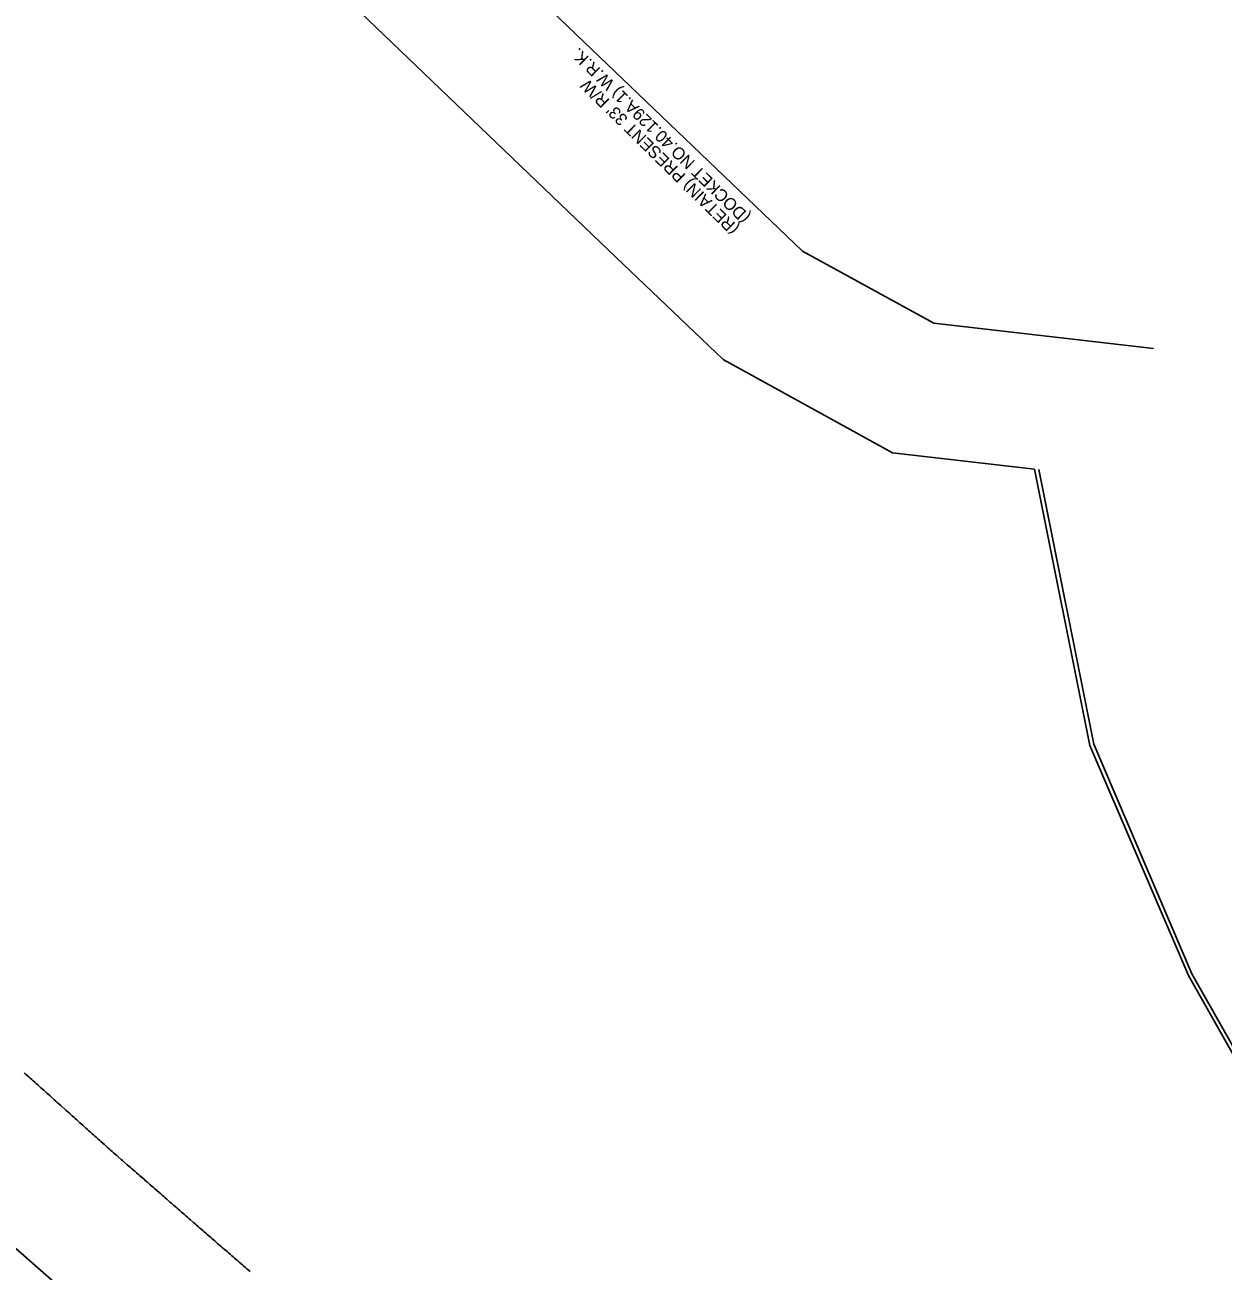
# Model space of a CAD drawing. Extents: x 2004008 to 2024436, y 806921 to 864820.
# Drawn here: x 2020668 to 2021261, y 815402 to 816019 of the extents above; entities that cross this region are included whole.
import ezdxf

# ---------------------------------------------------------------- set-up
doc = ezdxf.new("R2010")
doc.units = 0
for name, color, linetype in [('RD_PD_DR_ErosCtrl', 7, 'Continuous'), ('RD_PD_Final_LnLine', 7, 'Continuous'), ('RD_PD_MedBWall', 7, 'Continuous')]:
    doc.layers.add(name, color=color, linetype=linetype)

msp = doc.modelspace()

# ---------------------------------------------------------------- linework, layer by layer
at = {"layer": 'RD_PD_Final_LnLine'}
for p, q in [((2021006.56, 815951.38), (2020723.12, 816222.92)), ((2021053.12, 815906.9), (2021006.56, 815951.38)), ((2021118.04, 815871.24), (2021053.12, 815906.9)), ((2021226.67, 815858.67), (2021118.04, 815871.24))]:
    msp.add_line(p, q, dxfattribs=at)
msp.add_lwpolyline([(2021321.03, 815416.58), (2021245.78, 815549.48), (2021197.15, 815663), (2021170.03, 815798.78)], dxfattribs=at)
msp.add_arc((2025178.69, 820523.97), 6819.05, 224.953163, 232.80009, dxfattribs=at)
at = {"layer": 'RD_PD_MedBWall'}
for p, q in [((2020960.93, 815903.68), (2020679.45, 816173.35)), ((2021013.78, 815853.21), (2020960.93, 815903.68)), ((2021097.61, 815807.16), (2021013.78, 815853.21)), ((2021167.94, 815799.02), (2021097.61, 815807.16))]:
    msp.add_line(p, q, dxfattribs=at)
for points in [[(2021319.29, 815415.59), (2021243.99, 815548.59), (2021195.23, 815662.41), (2021167.94, 815799.02)], [(2020667.99, 815500.48), (2020668.74, 815499.82), (2020669.54, 815499.09), (2020670.23, 815498.48), (2020670.97, 815497.82), (2020671.78, 815497.09), (2020672.52, 815496.43), (2020673.2, 815495.82), (2020674.01, 815495.09), (2020674.69, 815494.48), (2020675.44, 815493.82), (2020676.24, 815493.09), (2020676.99, 815492.42), (2020677.67, 815491.81), (2020678.42, 815491.15), (2020679.27, 815490.38), (2020679.9, 815489.81), (2020680.65, 815489.15), (2020681.45, 815488.42), (2020682.14, 815487.81), (2020682.88, 815487.15), (2020683.69, 815486.42), (2020684.37, 815485.81), (2020685.12, 815485.15), (2020685.97, 815484.38), (2020686.66, 815483.76), (2020688.1, 815482.47), (2020688.84, 815481.81), (2020689.58, 815481.15), (2020690.39, 815480.42), (2020691.07, 815479.81), (2020691.82, 815479.15), (2020692.67, 815478.38), (2020693.36, 815477.75), (2020694.05, 815477.14), (2020694.79, 815476.48), (2020695.6, 815475.75), (2020696.28, 815475.14), (2020697.03, 815474.48), (2020697.88, 815473.71), (2020698.51, 815473.14), (2020699.26, 815472.48), (2020700.06, 815471.75), (2020700.75, 815471.14), (2020701.49, 815470.48), (2020702.3, 815469.75), (2020702.98, 815469.14), (2020703.73, 815468.48), (2020704.58, 815467.71), (2020705.21, 815467.14), (2020705.96, 815466.48), (2020706.84, 815465.69), (2020707.07, 815465.48), (2020707.69, 815464.94), (2020708.55, 815464.18), (2020709.3, 815463.52), (2020710, 815462.91), (2020710.76, 815462.25), (2020711.5, 815461.6), (2020712.25, 815460.95), (2020713.01, 815460.28), (2020713.77, 815459.62), (2020714.57, 815458.91), (2020716.02, 815457.64), (2020716.72, 815457.03), (2020717.52, 815456.34), (2020719.03, 815455.01), (2020719.79, 815454.35), (2020720.59, 815453.64), (2020721.34, 815452.98), (2020721.98, 815452.42), (2020722.74, 815451.77), (2020723.6, 815451.01), (2020724.35, 815450.35), (2020725.05, 815449.74), (2020725.81, 815449.08), (2020726.55, 815448.43), (2020727.3, 815447.78), (2020728.11, 815447.06), (2020728.81, 815446.45), (2020729.57, 815445.79), (2020730.37, 815445.08), (2020731.12, 815444.42), (2020731.76, 815443.86), (2020732.52, 815443.21), (2020734.83, 815441.18), (2020735.59, 815440.52), (2020736.39, 815439.81), (2020737.08, 815439.21), (2020737.78, 815438.6), (2020738.6, 815437.89), (2020739.4, 815437.18), (2020740.15, 815436.52), (2020740.85, 815435.91), (2020741.54, 815435.31), (2020742.03, 815434.89), (2020742.74, 815434.26), (2020743.5, 815433.61), (2020744.25, 815432.95), (2020745.01, 815432.3), (2020745.81, 815431.6), (2020746.51, 815430.99), (2020747.27, 815430.33), (2020748.02, 815429.68), (2020748.78, 815429.02), (2020749.53, 815428.37), (2020750.29, 815427.71), (2020751.79, 815426.41), (2020752.55, 815425.75), (2020753.3, 815425.1), (2020754.06, 815424.44), (2020754.81, 815423.79), (2020755.57, 815423.13), (2020756.37, 815422.44), (2020757.07, 815421.82), (2020757.83, 815421.17), (2020758.58, 815420.51), (2020759.34, 815419.86), (2020760.14, 815419.16), (2020760.84, 815418.55), (2020761.6, 815417.89), (2020762.29, 815417.29), (2020763.11, 815416.59), (2020763.86, 815415.93), (2020764.62, 815415.28), (2020765.42, 815414.58), (2020766.12, 815413.97), (2020766.88, 815413.31), (2020767.63, 815412.66), (2020768.39, 815412), (2020769.14, 815411.35), (2020769.9, 815410.69), (2020770.7, 815410), (2020771.4, 815409.38), (2020772.1, 815408.78), (2020772.91, 815408.08), (2020773.67, 815407.42), (2020774.42, 815406.77), (2020775.18, 815406.11), (2020775.98, 815405.42), (2020776.68, 815404.8), (2020777.44, 815404.15), (2020778.19, 815403.49), (2020778.95, 815402.84), (2020779.75, 815402.14)]]:
    msp.add_lwpolyline(points, dxfattribs=at)

# ---------------------------------------------------------------- texts
at = {"layer": 'RD_PD_DR_ErosCtrl'}
for s, p in [('(DOCKET NO.40.129A.1) W.R.K.', (2021027.65, 815924.25)), ("(RETAIN) PRESENT 33' R/W", (2021022.11, 815918.6))]:
    msp.add_text(s, height=6, rotation=135.54891, dxfattribs=at).set_placement(p)

doc.saveas('drawing.dxf')
